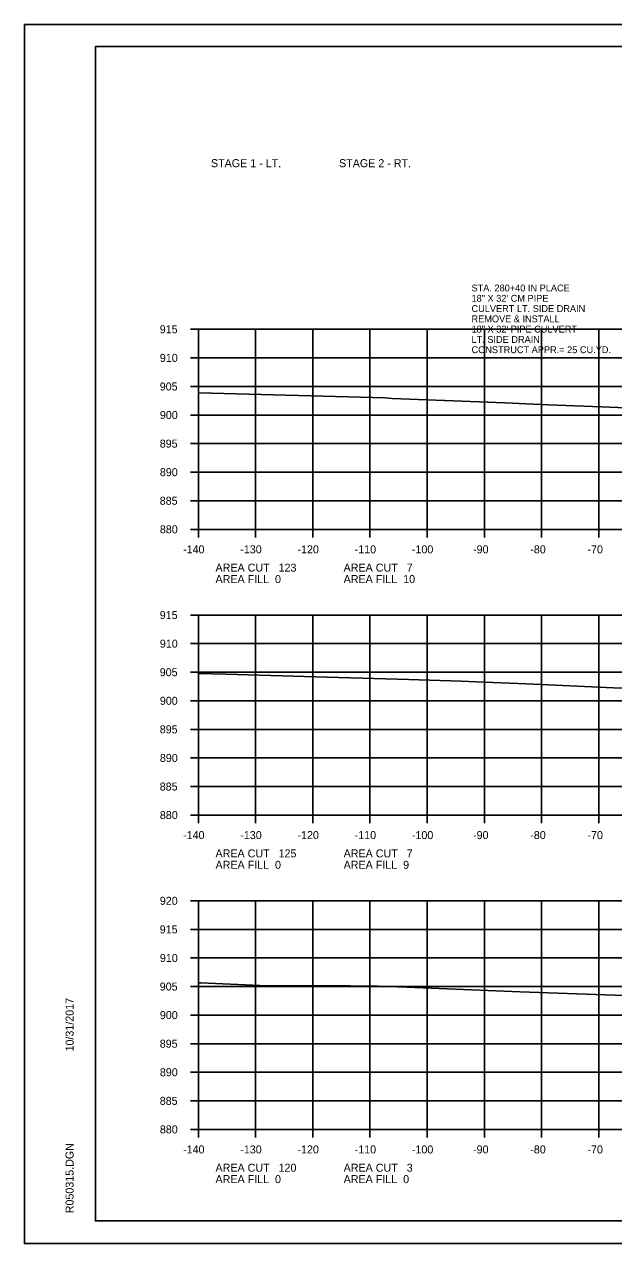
# Model space of a CAD drawing. Extents: x 1486524 to 1499135, y 326561 to 337924.
# Drawn here: x 1488812.5 to 1488915.5, y 331499.3 to 331712.6 of the extents above; entities that cross this region are included whole.
import ezdxf

# ---------------------------------------------------------------- set-up
doc = ezdxf.new("R2010")
doc.units = 0
for name, color, linetype in [('Default', 7, 'Continuous'), ('E_Const Align', 7, 'Continuous'), ('E_Const Align Station', 7, 'Continuous'), ('E_Ownership Information', 7, 'Continuous'), ('E_Property Line', 7, 'Continuous'), ('E_Quarter Calls', 7, 'Continuous'), ('E_Tract Number', 7, 'Continuous')]:
    doc.layers.add(name, color=color, linetype=linetype)

msp = doc.modelspace()

# ---------------------------------------------------------------- linework, layer by layer
at = {"layer": 'E_Const Align'}
for p, q in [((1488841.49, 331659.26), (1488842.89, 331659.26)), ((1488842.89, 331624.26), (1488842.89, 331659.26)), ((1488841.49, 331654.26), (1488842.89, 331654.26)), ((1488841.49, 331649.26), (1488842.89, 331649.26)), ((1488841.49, 331644.26), (1488842.89, 331644.26)), ((1488841.49, 331639.26), (1488842.89, 331639.26)), ((1488841.49, 331634.26), (1488842.89, 331634.26)), ((1488841.49, 331629.26), (1488842.89, 331629.26)), ((1488841.49, 331624.26), (1488842.89, 331624.26)), ((1488842.89, 331624.26), (1489122.89, 331624.26)), ((1488842.89, 331622.86), (1488842.89, 331624.26)), ((1488852.89, 331622.86), (1488852.89, 331624.26)), ((1488862.89, 331622.86), (1488862.89, 331624.26)), ((1488872.89, 331622.86), (1488872.89, 331624.26)), ((1488882.89, 331622.86), (1488882.89, 331624.26)), ((1488892.89, 331622.86), (1488892.89, 331624.26)), ((1488902.89, 331622.86), (1488902.89, 331624.26)), ((1488912.89, 331622.86), (1488912.89, 331624.26)), ((1488841.49, 331609.26), (1488842.89, 331609.26)), ((1488842.89, 331574.26), (1488842.89, 331609.26)), ((1488841.49, 331604.26), (1488842.89, 331604.26)), ((1488841.49, 331599.26), (1488842.89, 331599.26)), ((1488841.49, 331594.26), (1488842.89, 331594.26)), ((1488841.49, 331589.26), (1488842.89, 331589.26)), ((1488841.49, 331584.26), (1488842.89, 331584.26)), ((1488841.49, 331579.26), (1488842.89, 331579.26)), ((1488841.49, 331574.26), (1488842.89, 331574.26)), ((1488842.89, 331574.26), (1489122.89, 331574.26)), ((1488842.89, 331572.86), (1488842.89, 331574.26)), ((1488852.89, 331572.86), (1488852.89, 331574.26)), ((1488862.89, 331572.86), (1488862.89, 331574.26)), ((1488872.89, 331572.86), (1488872.89, 331574.26)), ((1488882.89, 331572.86), (1488882.89, 331574.26)), ((1488892.89, 331572.86), (1488892.89, 331574.26)), ((1488902.89, 331572.86), (1488902.89, 331574.26)), ((1488912.89, 331572.86), (1488912.89, 331574.26)), ((1488841.49, 331559.26), (1488842.89, 331559.26)), ((1488842.89, 331519.26), (1488842.89, 331559.26)), ((1488841.49, 331554.26), (1488842.89, 331554.26)), ((1488841.49, 331549.26), (1488842.89, 331549.26)), ((1488841.49, 331544.26), (1488842.89, 331544.26)), ((1488841.49, 331539.26), (1488842.89, 331539.26)), ((1488841.49, 331534.26), (1488842.89, 331534.26)), ((1488841.49, 331529.26), (1488842.89, 331529.26)), ((1488841.49, 331524.26), (1488842.89, 331524.26)), ((1488841.49, 331519.26), (1488842.89, 331519.26)), ((1488842.89, 331519.26), (1489122.89, 331519.26)), ((1488842.89, 331517.86), (1488842.89, 331519.26)), ((1488852.89, 331517.86), (1488852.89, 331519.26)), ((1488862.89, 331517.86), (1488862.89, 331519.26)), ((1488872.89, 331517.86), (1488872.89, 331519.26)), ((1488882.89, 331517.86), (1488882.89, 331519.26)), ((1488892.89, 331517.86), (1488892.89, 331519.26)), ((1488902.89, 331517.86), (1488902.89, 331519.26)), ((1488912.89, 331517.86), (1488912.89, 331519.26))]:
    msp.add_line(p, q, dxfattribs=at)
at = {"layer": 'E_Ownership Information'}
for p, q in [((1488842.89, 331659.26), (1489122.89, 331659.26)), ((1488842.89, 331624.26), (1488842.89, 331659.26)), ((1488852.89, 331624.26), (1488852.89, 331659.26)), ((1488862.89, 331624.26), (1488862.89, 331659.26)), ((1488872.89, 331624.26), (1488872.89, 331659.26)), ((1488882.89, 331624.26), (1488882.89, 331659.26)), ((1488892.89, 331624.26), (1488892.89, 331659.26)), ((1488902.89, 331624.26), (1488902.89, 331659.26)), ((1488912.89, 331624.26), (1488912.89, 331659.26)), ((1488842.89, 331654.26), (1489122.89, 331654.26)), ((1488842.89, 331649.26), (1489122.89, 331649.26)), ((1488842.89, 331644.26), (1489122.89, 331644.26)), ((1488842.89, 331639.26), (1489122.89, 331639.26)), ((1488842.89, 331634.26), (1489122.89, 331634.26)), ((1488842.89, 331629.26), (1489122.89, 331629.26)), ((1488842.89, 331624.26), (1489122.89, 331624.26)), ((1488842.89, 331609.26), (1489122.89, 331609.26)), ((1488842.89, 331574.26), (1488842.89, 331609.26)), ((1488852.89, 331574.26), (1488852.89, 331609.26)), ((1488862.89, 331574.26), (1488862.89, 331609.26)), ((1488872.89, 331574.26), (1488872.89, 331609.26)), ((1488882.89, 331574.26), (1488882.89, 331609.26)), ((1488892.89, 331574.26), (1488892.89, 331609.26)), ((1488902.89, 331574.26), (1488902.89, 331609.26)), ((1488912.89, 331574.26), (1488912.89, 331609.26)), ((1488842.89, 331604.26), (1489122.89, 331604.26)), ((1488842.89, 331599.26), (1489122.89, 331599.26)), ((1488842.89, 331594.26), (1489122.89, 331594.26)), ((1488842.89, 331589.26), (1489122.89, 331589.26)), ((1488842.89, 331584.26), (1489122.89, 331584.26)), ((1488842.89, 331579.26), (1489122.89, 331579.26)), ((1488842.89, 331574.26), (1489122.89, 331574.26)), ((1488842.89, 331559.26), (1489122.89, 331559.26)), ((1488842.89, 331519.26), (1488842.89, 331559.26)), ((1488852.89, 331519.26), (1488852.89, 331559.26)), ((1488862.89, 331519.26), (1488862.89, 331559.26)), ((1488872.89, 331519.26), (1488872.89, 331559.26)), ((1488882.89, 331519.26), (1488882.89, 331559.26)), ((1488892.89, 331519.26), (1488892.89, 331559.26)), ((1488902.89, 331519.26), (1488902.89, 331559.26)), ((1488912.89, 331519.26), (1488912.89, 331559.26)), ((1488842.89, 331554.26), (1489122.89, 331554.26)), ((1488842.89, 331549.26), (1489122.89, 331549.26)), ((1488842.89, 331544.26), (1489122.89, 331544.26)), ((1488842.89, 331539.26), (1489122.89, 331539.26)), ((1488842.89, 331534.26), (1489122.89, 331534.26)), ((1488842.89, 331529.26), (1489122.89, 331529.26)), ((1488842.89, 331524.26), (1489122.89, 331524.26)), ((1488842.89, 331519.26), (1489122.89, 331519.26))]:
    msp.add_line(p, q, dxfattribs=at)
at = {"layer": 'E_Property Line'}
for p, q in [((1488824.89, 331708.72), (1489141.07, 331708.72)), ((1488824.89, 331503.26), (1488824.89, 331708.72)), ((1488824.89, 331503.26), (1488824.89, 331503.26)), ((1489141.07, 331503.26), (1488824.89, 331503.26))]:
    msp.add_line(p, q, dxfattribs=at)
at = {"layer": 'E_Quarter Calls'}
for p, q in [((1488812.48, 331712.62), (1489145.82, 331712.62)), ((1488812.48, 331499.28), (1489145.82, 331499.28))]:
    msp.add_line(p, q, dxfattribs=at)
for points in [[(1488812.48, 331712.62), (1489145.82, 331712.62), (1489145.82, 331499.28), (1488812.48, 331499.28)], [(1489058.81, 331708.72), (1489058.81, 331698.84), (1489094.54, 331698.84), (1489094.54, 331695.92), (1489117.74, 331695.92), (1489117.74, 331671.59), (1489141.07, 331671.59), (1489141.07, 331503.26), (1488824.89, 331503.26), (1488824.89, 331708.72)]]:
    msp.add_lwpolyline(points, close=True, dxfattribs=at)
at = {"layer": 'E_Tract Number'}
for points in [[(1488842.89, 331648.16), (1488843.05, 331648.15), (1488875.55, 331647.25), (1488876.77, 331647.17), (1488891.97, 331646.57), (1488896.46, 331646.41), (1488904.03, 331646.07), (1488913.38, 331645.72), (1488920.5, 331645.4)], [(1488842.89, 331599.04), (1488847.72, 331598.92), (1488865.4, 331598.42), (1488879.67, 331597.98), (1488888.81, 331597.7), (1488891.44, 331597.58), (1488900.24, 331597.22), (1488915.48, 331596.54), (1488930.82, 331595.93)], [(1488842.89, 331544.91), (1488843.35, 331544.89), (1488853.61, 331544.46), (1488869.45, 331544.38), (1488874.31, 331544.34), (1488879.34, 331544.16), (1488899.13, 331543.33), (1488917.33, 331542.7)]]:
    msp.add_lwpolyline(points, dxfattribs=at)

# ---------------------------------------------------------------- texts
at = {"layer": 'Default'}
for s, height, p in [('STAGE 1 - LT.', 1.4, (1488845.09, 331687.63)), ('STAGE 2 - RT.', 1.4, (1488867.49, 331687.63)), ('STA. 280+40 IN PLACE', 1.2, (1488890.65, 331665.89)), ('18" X 32\' CM PIPE', 1.2, (1488890.65, 331664.09)), ('CULVERT LT. SIDE DRAIN', 1.2, (1488890.65, 331662.29)), ('REMOVE & INSTALL', 1.2, (1488890.65, 331660.49)), ('18" X 32\' PIPE CULVERT', 1.2, (1488890.65, 331658.69)), ('LT. SIDE DRAIN', 1.2, (1488890.65, 331656.89)), ('CONSTRUCT APPR.= 25 CU.YD.', 1.2, (1488890.65, 331655.09))]:
    msp.add_text(s, height=height, dxfattribs=at).set_placement(p)
at = {"layer": 'E_Const Align Station'}
for s, p in [('915', (1488836.14, 331658.56)), ('910', (1488836.16, 331653.56)), ('905', (1488836.14, 331648.56)), ('900', (1488836.16, 331643.56)), ('895', (1488836.14, 331638.56)), ('890', (1488836.16, 331633.56)), ('885', (1488836.14, 331628.56)), ('880', (1488836.16, 331623.56)), ('-140', (1488840.22, 331620.06)), ('-130', (1488850.22, 331620.06)), ('-120', (1488860.22, 331620.06)), ('-110', (1488870.22, 331620.06)), ('-100', (1488880.22, 331620.06)), ('-90', (1488890.92, 331620.06)), ('-80', (1488900.92, 331620.06)), ('-70', (1488910.92, 331620.06)), ('AREA CUT   123', (1488845.89, 331616.86)), ('AREA FILL  0', (1488845.89, 331614.86)), ('AREA CUT   7', (1488868.29, 331616.86)), ('AREA FILL  10', (1488868.29, 331614.86)), ('915', (1488836.14, 331608.56)), ('910', (1488836.16, 331603.56)), ('905', (1488836.14, 331598.56)), ('900', (1488836.16, 331593.56)), ('895', (1488836.14, 331588.56)), ('890', (1488836.16, 331583.56)), ('885', (1488836.14, 331578.56)), ('880', (1488836.16, 331573.56)), ('-140', (1488840.22, 331570.06)), ('-130', (1488850.22, 331570.06)), ('-120', (1488860.22, 331570.06)), ('-110', (1488870.22, 331570.06)), ('-100', (1488880.22, 331570.06)), ('-90', (1488890.92, 331570.06)), ('-80', (1488900.92, 331570.06)), ('-70', (1488910.92, 331570.06)), ('AREA CUT   125', (1488845.89, 331566.86)), ('AREA CUT   7', (1488868.29, 331566.86)), ('AREA FILL  0', (1488845.89, 331564.86)), ('AREA FILL  9', (1488868.29, 331564.86)), ('920', (1488836.16, 331558.56)), ('915', (1488836.14, 331553.56)), ('910', (1488836.16, 331548.56)), ('905', (1488836.14, 331543.56)), ('900', (1488836.16, 331538.56)), ('895', (1488836.14, 331533.56)), ('890', (1488836.16, 331528.56)), ('885', (1488836.14, 331523.56)), ('880', (1488836.16, 331518.56)), ('-140', (1488840.22, 331515.06)), ('-130', (1488850.22, 331515.06)), ('-120', (1488860.22, 331515.06)), ('-110', (1488870.22, 331515.06)), ('-100', (1488880.22, 331515.06)), ('-90', (1488890.92, 331515.06)), ('-80', (1488900.92, 331515.06)), ('-70', (1488910.92, 331515.06)), ('AREA CUT   120', (1488845.89, 331511.86)), ('AREA CUT   3', (1488868.29, 331511.86)), ('AREA FILL  0', (1488845.89, 331509.86)), ('AREA FILL  0', (1488868.29, 331509.86))]:
    msp.add_text(s, height=1.4, dxfattribs=at).set_placement(p)
at = {"layer": 'E_Property Line'}
for s, p in [('10/31/2017', (1488821.08, 331532.9)), ('R050315.DGN', (1488821.08, 331504.59))]:
    msp.add_text(s, height=1.4, rotation=90, dxfattribs=at).set_placement(p)

doc.saveas('drawing.dxf')
